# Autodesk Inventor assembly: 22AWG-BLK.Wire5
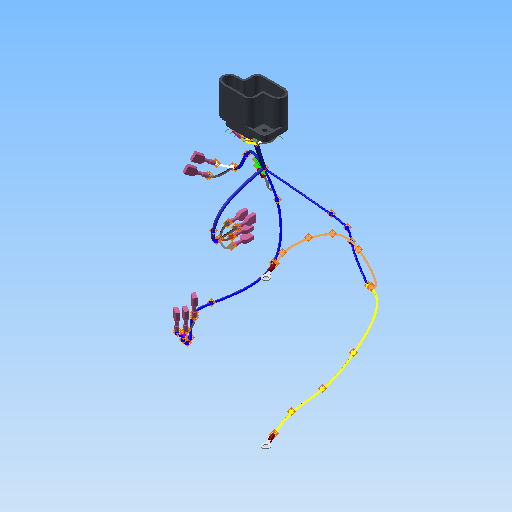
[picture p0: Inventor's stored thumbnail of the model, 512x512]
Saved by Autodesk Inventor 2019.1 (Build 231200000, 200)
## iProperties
Created: 2006-02
Part Number: 22AWG-BLK.Wire5
Description: 22AWG-BLK
Designer: floress
Stock Number: 22AWG-BLK
Material: Default
Author: floress
Part Number: 22AWG-ORG.Wire9
Description: 22AWG-ORG
Stock Number: 22AWG-ORG
Part Number: 18AWG-GRN.Wire4
Description: 18AWG-GRN
Stock Number: 18AWG-GRN
Part Number: 22AWG-YEL.Wire8
Description: 22AWG-YEL
Stock Number: 22AWG-YEL
Part Number: 18AWG-BLK.Wire2
Description: 18AWG-BLK
Stock Number: 18AWG-BLK
Part Number: 18AWG-BLK.Wire1
Part Number: 18AWG-WHT.Wire3
Description: 18AWG-WHT
Stock Number: 18AWG-WHT
Part Number: Male Drawer.Male Drawer
Description: Male Drawer
Stock Number: Male Drawer
Part Number: 22AWG-GRY.Wire11
Description: 22AWG-GRY
Stock Number: 22AWG-GRY
Part Number: 22AWG-VIO.Wire7
Description: 22AWG-VIO
Stock Number: 22AWG-VIO
Part Number: 22AWG-BLU.Wire6
Description: 22AWG-BLU
Stock Number: 22AWG-BLU
Part Number: 22AWG-BRN.Wire10
Description: 22AWG-BRN
Stock Number: 22AWG-BRN
ParentFileIdentifier: 5|1|0|0|144|1|0|0|80|0|65|0|84|0|72|0|83|0|59|0|67|0|58|0|92|0|77|0|121|0|32|0|68|0|111|0|99|0|117|0|109|0|101|0|110|0|116|0|115|0|92|0|73|0|110|0|118|0|101|0|1
Created: 2005-11
Part Number: Hopper.Harness1
Document SubType Name: Assembly
HarnessSettings: <HarnessSettings><Defaults><Segments><Diameter value="0.200 in" fromwires="True"/><Offset value="0.100 in"/><ColorStyle value="Blue"/><RoundUp value=""/><BendRa
CableFileVersion: 11.0.9
CableDummyParamRefKey: Key:16|2|0|0|16|0|0|0|246|63|0|0|0|0|0|0|129|0|0|0|0|0|0|0|Level:1
GlobalPropertyList: <PropertyList/>
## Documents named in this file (5)
- F:\Slotmachine\Slot Machine Sample\Workspace\Cabinet\Hopper\AIP\Cable and Harness\Hopper.Harness1.iam
- F:\Slotmachine\Slot Machine Sample\Workspace\Cabinet\Hopper\AIP\Cable and Harness\Hopper.Harness1.ipt
- F:\Slotmachine\Slot Machine Sample\Workspace\Hardware\Connectors\Terminal Ring.ipt
- F:\Slotmachine\Slot Machine Sample\Workspace\Hardware\Connectors\Quick Connect, Female, 22AWG.ipt
- F:\Slotmachine\Slot Machine Sample\Workspace\Hardware\Connectors\A208209-1.ipt
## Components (35 placed, 25 different names)
1. A208209-1:1
2. Terminal Ring:1
3. Terminal Ring:2
4. Terminal Ring:3
5. Quick Connect, Female, 22AWG:1
6. Quick Connect, Female, 22AWG:2
7. Quick Connect, Female, 22AWG:3
8. Quick Connect, Female, 22AWG:4
9. Quick Connect, Female, 22AWG:5
10. Quick Connect, Female, 22AWG:6
11. Quick Connect, Female, 22AWG:7
12. Quick Connect, Female, 22AWG:8
13. Quick Connect, Female, 22AWG:9
14. Harness1
15. HA_VC_111:1
16. HA_VC_123:1
17. HA_VC_126:1
18. HA_VC_225:1
19. HA_VC_228:1
20. HA_VC_231:1
21. HA_VC_234:1
22. HA_VC_237:1
23. HA_VC_240:1
24. HA_VC_243:1
25. HA_VC_246:1
26. HA_VC_264:1
27. HA_VC_265:1
28. HA_VC_266:1
29. HA_VC_267:1
30. HA_VC_268:1
31. HA_VC_269:1
32. HA_VC_270:1
33. HA_VC_271:1
34. HA_VC_272:1
35. HA_VC_273:1
